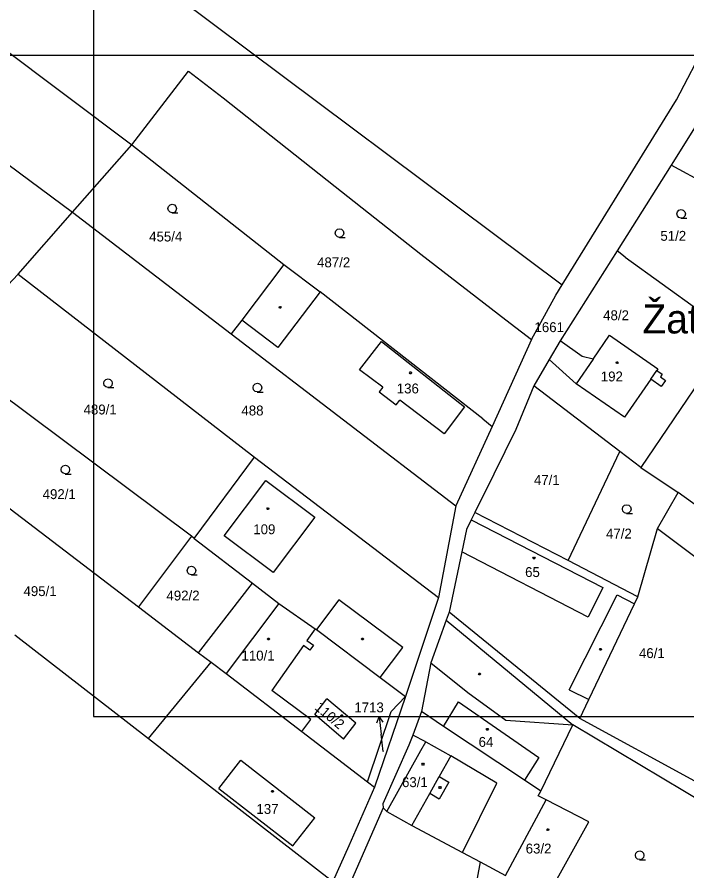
# Model space of a CAD drawing. Extents: x -802857 to -799647, y -1020285 to -1015884.
# Drawn here: x -801717 to -801601.9, y -1017640.2 to -1017493.5 of the extents above; entities that cross this region are included whole.
import ezdxf

# ---------------------------------------------------------------- set-up
doc = ezdxf.new("R2010")
doc.units = 0
for name, color, linetype in [('Default', 7, 'Continuous'), ('KLADY_ZMVM', 7, 'Continuous'), ('KN_HRANICE', 7, 'Continuous'), ('KN_KULTURY', 7, 'Continuous'), ('KN_PARCELY', 7, 'Continuous'), ('KN_SLUCKY', 7, 'Continuous'), ('LEGENDA', 7, 'Continuous')]:
    doc.layers.add(name, color=color, linetype=linetype)

# ---------------------------------------------------------------- blocks, each defined once
blk = doc.blocks.new('304')
at = {"layer": 'Default'}
blk.add_lwpolyline([(0, 0), (-0.38, 0.1), (-0.65, 0.37), (-0.75, 0.74), (-0.65, 1.11), (-0.38, 1.38), (-0.01, 1.48), (0.36, 1.38), (0.63, 1.11), (0.73, 0.73), (0.63, 0.35), (0.36, 0.08), (-0.02, -0.02), (0.98, -0.02)], dxfattribs=at)
blk = doc.blocks.new('10292')
at = {"layer": 'Default'}
blk.add_line((0, 3), (0, 0), dxfattribs=at)
blk.add_lwpolyline([(-0.5, 2), (0, 3), (0.5, 2)], dxfattribs=at)
blk = doc.blocks.new('402')
at = {"layer": 'Default'}
blk.add_lwpolyline([(0.09, 0.15), (0.18, 0), (0.09, -0.15), (-0.09, -0.15), (-0.18, 0), (-0.09, 0.15), (0.09, 0.15)], dxfattribs=at)

msp = doc.modelspace()

# ---------------------------------------------------------------- linework, layer by layer
at = {"layer": 'KLADY_ZMVM'}
msp.add_lwpolyline([(-801875, -1017500), (-801250, -1017500), (-801043.11, -1017500)], dxfattribs=at)
at = {"layer": 'KN_HRANICE'}
for p, q in [((-801752.52, -1017442.84), (-801623.34, -1017539.52)), ((-801768.75, -1017461.94), (-801697.3, -1017515.42)), ((-801779.08, -1017474.09), (-801707.48, -1017527.01)), ((-801603.69, -1017507.7), (-801595.69, -1017492.25)), ((-801697.3, -1017515.42), (-801687.56, -1017502.76)), ((-801687.56, -1017502.76), (-801681.57, -1017507.37)), ((-801681.57, -1017507.37), (-801662.34, -1017522.59)), ((-801623.34, -1017539.52), (-801603.69, -1017507.7)), ((-801599.92, -1017511.43), (-801604.62, -1017518.91)), ((-801707.48, -1017527.01), (-801697.3, -1017515.42)), ((-801697.3, -1017515.42), (-801671.15, -1017535.99)), ((-801604.62, -1017518.91), (-801613.91, -1017533.68)), ((-801586.4, -1017528.88), (-801604.62, -1017518.91)), ((-801662.34, -1017522.59), (-801647.61, -1017534.21)), ((-801716.78, -1017537.68), (-801707.48, -1017527.01)), ((-801707.48, -1017527.01), (-801680.21, -1017547.94)), ((-801647.61, -1017534.21), (-801633.05, -1017545.52)), ((-801613.91, -1017533.68), (-801623.67, -1017549.1)), ((-801612.51, -1017534.74), (-801613.91, -1017533.68)), ((-801612.51, -1017534.74), (-801599.81, -1017543.92)), ((-801671.15, -1017535.99), (-801678.4, -1017545.55)), ((-801671.15, -1017535.99), (-801664.95, -1017540.69)), ((-801729.49, -1017550.94), (-801716.78, -1017537.68)), ((-801716.78, -1017537.68), (-801676.19, -1017569.11)), ((-801624.44, -1017541.3), (-801623.34, -1017539.52)), ((-801637, -1017562.55), (-801664.95, -1017540.69)), ((-801628.6, -1017548.89), (-801624.44, -1017541.3)), ((-801678.4, -1017545.55), (-801680.21, -1017547.94)), ((-801633.05, -1017545.52), (-801628.6, -1017548.89)), ((-801680.21, -1017547.94), (-801641.61, -1017577.47)), ((-801594.29, -1017547.96), (-801609.85, -1017570.88)), ((-801628.6, -1017548.89), (-801635.4, -1017563.83)), ((-801623.67, -1017549.1), (-801625.57, -1017552.36)), ((-801619.9, -1017551.8), (-801623.67, -1017549.1)), ((-801618.03, -1017552.3), (-801615.19, -1017548.14)), ((-801615.19, -1017548.14), (-801606.91, -1017553.95)), ((-801687.03, -1017582.73), (-801729.49, -1017550.94)), ((-801625.57, -1017552.36), (-801628.2, -1017556.86)), ((-801625.57, -1017552.36), (-801620.96, -1017556.51)), ((-801618.03, -1017552.3), (-801619.9, -1017551.8)), ((-801606.91, -1017553.95), (-801607.11, -1017554.24)), ((-801607.11, -1017554.24), (-801606.18, -1017554.88)), ((-801606.18, -1017554.88), (-801606.48, -1017555.33)), ((-801612.65, -1017562.22), (-801620.96, -1017556.51)), ((-801608.14, -1017555.73), (-801612.65, -1017562.22)), ((-801606.34, -1017556.98), (-801608.14, -1017555.73)), ((-801606.48, -1017555.33), (-801605.61, -1017555.93)), ((-801605.61, -1017555.93), (-801606.34, -1017556.98)), ((-801628.2, -1017556.86), (-801631.32, -1017564.34)), ((-801613.44, -1017568.14), (-801628.2, -1017556.86)), ((-801637, -1017562.55), (-801635.4, -1017563.83)), ((-801737.57, -1017563.21), (-801696.11, -1017594.87)), ((-801635.4, -1017563.83), (-801641.61, -1017577.47)), ((-801631.32, -1017564.34), (-801635.08, -1017572.03)), ((-801622.34, -1017586.91), (-801613.44, -1017568.14)), ((-801609.85, -1017570.88), (-801613.44, -1017568.14)), ((-801686.57, -1017583.08), (-801676.19, -1017569.11)), ((-801676.19, -1017569.11), (-801644.59, -1017593.25)), ((-801609.85, -1017570.88), (-801603.42, -1017575.18)), ((-801635.08, -1017572.03), (-801638.36, -1017578.66)), ((-801606.97, -1017581.38), (-801603.42, -1017575.18)), ((-801593.16, -1017582.7), (-801603.42, -1017575.18)), ((-801641.61, -1017577.47), (-801644.59, -1017593.25)), ((-801638.36, -1017578.66), (-801638.97, -1017579.89)), ((-801622.34, -1017586.91), (-801638.36, -1017578.66)), ((-801638.97, -1017579.89), (-801639.81, -1017581.56)), ((-801639.81, -1017581.56), (-801640.61, -1017585.38)), ((-801610.33, -1017593.16), (-801606.97, -1017581.38)), ((-801606.97, -1017581.38), (-801591.28, -1017593.15)), ((-801687.03, -1017582.73), (-801696.11, -1017594.87)), ((-801686.57, -1017583.08), (-801687.03, -1017582.73)), ((-801686.57, -1017583.08), (-801676.56, -1017590.77)), ((-801640.61, -1017585.38), (-801642.78, -1017595.77)), ((-801610.33, -1017593.16), (-801622.34, -1017586.91)), ((-801685.82, -1017602.73), (-801676.56, -1017590.77)), ((-801676.56, -1017590.77), (-801672.03, -1017594.25)), ((-801644.59, -1017593.25), (-801650.28, -1017610.24)), ((-801610.94, -1017594.36), (-801610.33, -1017593.16)), ((-801696.11, -1017594.87), (-801685.82, -1017602.73)), ((-801672.03, -1017594.25), (-801665.81, -1017598.61)), ((-801618.76, -1017610.78), (-801610.94, -1017594.36)), ((-801642.78, -1017595.77), (-801643.3, -1017597.13)), ((-801620.3, -1017614.03), (-801642.78, -1017595.77)), ((-801643.3, -1017597.13), (-801645.9, -1017604.47)), ((-801643.3, -1017597.13), (-801621.52, -1017615.14)), ((-801665.81, -1017598.61), (-801665.58, -1017598.77)), ((-801665.58, -1017598.77), (-801654.61, -1017606.97)), ((-801717.38, -1017599.65), (-801694.39, -1017617.48)), ((-801685.82, -1017602.73), (-801683.64, -1017604.39)), ((-801694.39, -1017617.48), (-801683.64, -1017604.39)), ((-801683.64, -1017604.39), (-801681.1, -1017606.33)), ((-801645.9, -1017604.47), (-801647.52, -1017612.87)), ((-801681.1, -1017606.33), (-801668.08, -1017616.3)), ((-801654.61, -1017606.97), (-801650.28, -1017610.24)), ((-801665.85, -1017613.34), (-801663.76, -1017610.64)), ((-801658.81, -1017614.87), (-801663.76, -1017610.64)), ((-801650.28, -1017610.24), (-801655.61, -1017625.85)), ((-801652.74, -1017612.84), (-801650.28, -1017610.24)), ((-801620.3, -1017614.03), (-801618.76, -1017610.78)), ((-801660.9, -1017617.57), (-801665.85, -1017613.34)), ((-801656.8, -1017624.94), (-801652.74, -1017612.84)), ((-801647.52, -1017612.87), (-801649.02, -1017616.9)), ((-801643.72, -1017615.4), (-801647.52, -1017612.87)), ((-801660.9, -1017617.57), (-801658.81, -1017614.87)), ((-801629.84, -1017624.66), (-801643.72, -1017615.4)), ((-801627, -1017626.55), (-801621.52, -1017615.14)), ((-801584.1, -1017637.52), (-801621.52, -1017615.14)), ((-801600.56, -1017624.82), (-801620.3, -1017614.03)), ((-801668.08, -1017616.3), (-801656.8, -1017624.94)), ((-801649.02, -1017616.9), (-801649.67, -1017618.65)), ((-801646.79, -1017618.07), (-801649.02, -1017616.9)), ((-801694.39, -1017617.48), (-801662.74, -1017642.08)), ((-801646.79, -1017618.07), (-801642.46, -1017620.47)), ((-801649.67, -1017618.65), (-801654.18, -1017628.7)), ((-801634.57, -1017625.14), (-801642.46, -1017620.47)), ((-801656.8, -1017624.94), (-801655.61, -1017625.85)), ((-801640.48, -1017637.07), (-801634.57, -1017625.14)), ((-801627, -1017626.55), (-801629.84, -1017624.66)), ((-801655.61, -1017625.85), (-801659.97, -1017635.92)), ((-801627.46, -1017627.34), (-801627, -1017626.55)), ((-801626.1, -1017628.02), (-801627.46, -1017627.34)), ((-801618.78, -1017631.82), (-801626.1, -1017628.02)), ((-801654.11, -1017629.4), (-801671.57, -1017669.41)), ((-801654.18, -1017628.7), (-801654.11, -1017629.4)), ((-801654.11, -1017629.4), (-801653.46, -1017630.01)), ((-801653.46, -1017630.01), (-801649.18, -1017632.41)), ((-801649.18, -1017632.41), (-801640.48, -1017637.07)), ((-801626.01, -1017644.85), (-801618.78, -1017631.82)), ((-801659.97, -1017635.92), (-801662.74, -1017642.08)), ((-801640.48, -1017637.07), (-801637.41, -1017638.71)), ((-801637.41, -1017638.71), (-801642.23, -1017664.46)), ((-801637.41, -1017638.71), (-801633.09, -1017641.02))]:
    msp.add_line(p, q, dxfattribs=at)
at = {"layer": 'KN_PARCELY'}
msp.add_line((-801654.08, -1017619.74), (-801654.44, -1017616.74), dxfattribs=at)
at = {"layer": 'KN_SLUCKY'}
for p, q in [((-801664.95, -1017540.69), (-801672.2, -1017550.25)), ((-801672.2, -1017550.25), (-801678.4, -1017545.55)), ((-801658.14, -1017554.09), (-801654.37, -1017549.26)), ((-801654.37, -1017549.26), (-801640.11, -1017560.46)), ((-801618.03, -1017552.3), (-801620.96, -1017556.51)), ((-801654.16, -1017557.12), (-801658.14, -1017554.09)), ((-801608.14, -1017555.73), (-801607.11, -1017554.24)), ((-801654.16, -1017557.12), (-801654.77, -1017557.92)), ((-801654.77, -1017557.92), (-801651.87, -1017560.13)), ((-801651.87, -1017560.13), (-801651.26, -1017559.33)), ((-801643.64, -1017565.14), (-801651.26, -1017559.33)), ((-801640.11, -1017560.46), (-801643.64, -1017565.14)), ((-801681.41, -1017582.62), (-801674.28, -1017573.12)), ((-801674.28, -1017573.12), (-801665.84, -1017579.45)), ((-801665.84, -1017579.45), (-801672.97, -1017588.95)), ((-801638.97, -1017579.89), (-801616.34, -1017591.55)), ((-801672.97, -1017588.95), (-801681.41, -1017582.62)), ((-801618.86, -1017596.61), (-801640.61, -1017585.38)), ((-801616.34, -1017591.55), (-801618.86, -1017596.61)), ((-801622.14, -1017609.12), (-801613.91, -1017592.8)), ((-801613.91, -1017592.8), (-801610.94, -1017594.36)), ((-801672.03, -1017594.25), (-801681.1, -1017606.33)), ((-801661.69, -1017593.67), (-801665.58, -1017598.77)), ((-801650.72, -1017601.82), (-801661.69, -1017593.67)), ((-801665.81, -1017598.61), (-801667.24, -1017600.66)), ((-801667.24, -1017600.66), (-801666.09, -1017601.46)), ((-801667.81, -1017601.48), (-801673.24, -1017609.22)), ((-801666.67, -1017602.28), (-801667.81, -1017601.48)), ((-801666.09, -1017601.46), (-801666.67, -1017602.28)), ((-801654.61, -1017606.97), (-801650.72, -1017601.82)), ((-801645.9, -1017604.47), (-801639.55, -1017609.58)), ((-801666.53, -1017614.22), (-801673.24, -1017609.22)), ((-801639.55, -1017609.58), (-801633.02, -1017614.35)), ((-801622.14, -1017609.12), (-801618.76, -1017610.78)), ((-801643.72, -1017615.4), (-801641.15, -1017611.16)), ((-801641.15, -1017611.16), (-801627.34, -1017620.77)), ((-801668.08, -1017616.3), (-801666.53, -1017614.22)), ((-801633.02, -1017614.35), (-801621.52, -1017615.14)), ((-801647.62, -1017619.56), (-801646.79, -1017618.07)), ((-801653.46, -1017630.01), (-801647.62, -1017619.56)), ((-801682.34, -1017626.05), (-801678.56, -1017621.22)), ((-801678.56, -1017621.22), (-801665.82, -1017631.12)), ((-801642.46, -1017620.47), (-801644.46, -1017624.03)), ((-801627.34, -1017620.77), (-801629.84, -1017624.66)), ((-801646.11, -1017626.96), (-801644.46, -1017624.03)), ((-801644.46, -1017624.03), (-801642.81, -1017624.96)), ((-801642.81, -1017624.96), (-801644.45, -1017627.89)), ((-801682.34, -1017626.05), (-801669.6, -1017635.95)), ((-801649.18, -1017632.41), (-801646.11, -1017626.96)), ((-801644.45, -1017627.89), (-801646.11, -1017626.96)), ((-801633.09, -1017641.02), (-801626.1, -1017628.02)), ((-801669.6, -1017635.95), (-801665.82, -1017631.12))]:
    msp.add_line(p, q, dxfattribs=at)
at = {"layer": 'LEGENDA'}
msp.add_lwpolyline([(-801703.84, -1017613.71), (-800862.84, -1017613.71), (-800862.84, -1017019.71), (-801703.84, -1017019.71)], close=True, dxfattribs=at)

# ---------------------------------------------------------------- block references
at = {"layer": 'KN_KULTURY'}
for name, p in [('304', (-801690.33, -1017527.12)), ('304', (-801602.91, -1017528.04)), ('304', (-801661.59, -1017531.34)), ('402', (-801671.8, -1017543.37)), ('402', (-801613.91, -1017552.86)), ('402', (-801649.39, -1017554.63)), ('304', (-801701.36, -1017557.15)), ('304', (-801675.7, -1017557.91)), ('304', (-801708.69, -1017572)), ('304', (-801612.25, -1017578.78)), ('402', (-801673.9, -1017577.98)), ('402', (-801628.19, -1017586.46)), ('304', (-801687.03, -1017589.35)), ('402', (-801673.8, -1017600.38)), ('402', (-801657.65, -1017600.38)), ('402', (-801616.75, -1017602.17)), ('402', (-801637.54, -1017606.39)), ('402', (-801661.21, -1017613.54)), ('402', (-801636.2, -1017615.92)), ('402', (-801647.25, -1017621.89)), ('402', (-801673.11, -1017626.57)), ('402', (-801644.34, -1017625.91)), ('402', (-801625.79, -1017633.15)), ('304', (-801610.02, -1017638.3))]:
    msp.add_blockref(name, p, dxfattribs=at)
at = {"layer": 'KN_PARCELY', "rotation": 6.875494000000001}
msp.add_blockref('10292', (-801654.44, -1017616.74), dxfattribs=at)

# ---------------------------------------------------------------- texts
at = {"layer": 'KLADY_ZMVM'}
msp.add_text('Žatec 0-8/34', height=5, dxfattribs=at).set_placement((-801609.55, -1017547.86))
at = {"layer": 'KN_PARCELY'}
for s, height, p in [('455/4', 1.7, (-801694.3, -1017532.05)), ('51/2', 1.7, (-801606.47, -1017531.93)), ('487/2', 1.7, (-801665.45, -1017536.49)), ('48/2', 1.7, (-801616.3, -1017545.58)), ('1661', 1.7, (-801628.1, -1017547.63)), ('192', 1.7, (-801616.71, -1017556.1)), ('136', 1.7, (-801651.76, -1017558.17)), ('489/1', 1.7, (-801705.57, -1017561.78)), ('488', 1.7, (-801678.45, -1017561.95)), ('47/1', 1.7, (-801628.2, -1017573.9)), ('492/1', 1.7, (-801712.6, -1017576.33)), ('109', 1.7, (-801676.41, -1017582.37)), ('47/2', 1.7, (-801615.81, -1017583.11)), ('65', 1.7, (-801629.71, -1017589.73)), ('495/1', 1.7, (-801715.89, -1017593)), ('492/2', 1.7, (-801691.33, -1017593.76)), ('46/1', 1.7, (-801610.15, -1017603.66)), ('110/1', 1.7, (-801678.44, -1017604.08)), ('1713', 1.7, (-801659.05, -1017612.99)), ('64', 1.7, (-801637.7, -1017618.92)), ('1713', 0.1, (-801654.28, -1017619.74)), ('63/1', 1.7, (-801650.86, -1017625.84)), ('137', 1.7, (-801675.87, -1017630.44)), ('63/2', 1.7, (-801629.61, -1017637.25))]:
    msp.add_text(s, height=height, dxfattribs=at).set_placement(p)
msp.add_text('110/2', height=1.7, rotation=319.882, dxfattribs=at).set_placement((-801666.01, -1017612.35))

doc.saveas('drawing.dxf')
